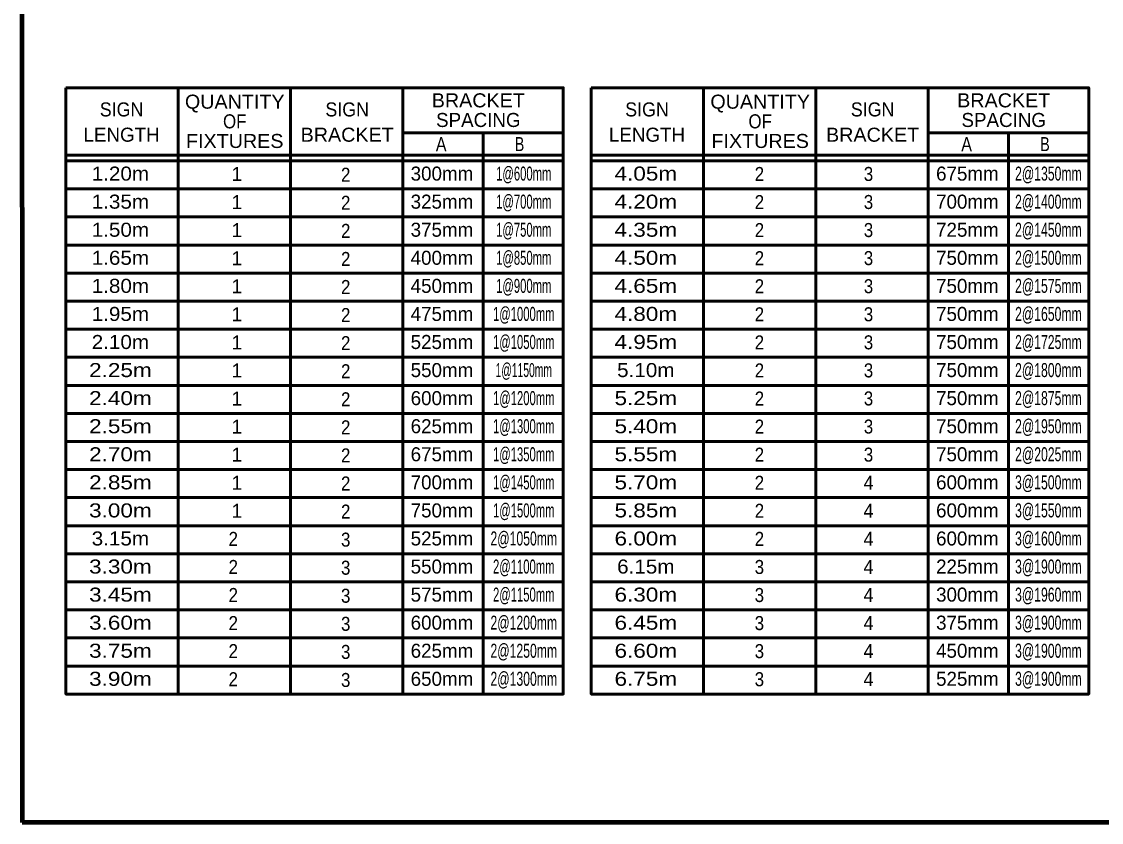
# Model space of a CAD drawing. Extents: x -94 to 762, y -50 to 494.
# Drawn here: x -36.3 to 194.5, y -38.7 to 132.5 of the extents above; entities that cross this region are included whole.
import ezdxf
from ezdxf.enums import TextEntityAlignment as Align

# ---------------------------------------------------------------- set-up
doc = ezdxf.new("R2010")
doc.units = 0
doc.header["$LTSCALE"] = 1.2
doc.layers.add('1', color=7, linetype='Continuous', lineweight=53)

msp = doc.modelspace()

# ---------------------------------------------------------------- linework, layer by layer
at = {"layer": '1'}
for p, q in [((-2.831, -11.296), (-2.831, 118.303)), ((21.169, -11.296), (21.169, 118.303)), ((45.169, -11.296), (45.169, 118.303)), ((109.451, -11.296), (109.451, 118.303)), ((133.451, -11.296), (133.451, 118.303)), ((157.451, -11.296), (157.451, 118.303)), ((45.169, 108.704), (79.451, 108.704)), ((62.31, -11.296), (62.31, 108.704)), ((157.451, 108.704), (191.733, 108.704)), ((174.592, -11.296), (174.592, 108.704)), ((-26.831, 103.904), (79.451, 103.904)), ((85.451, 103.904), (191.733, 103.904)), ((-26.831, 102.704), (79.451, 102.704)), ((85.451, 102.704), (191.733, 102.704)), ((-26.831, 96.704), (79.451, 96.704)), ((85.451, 96.704), (191.733, 96.704)), ((-26.831, 90.704), (79.451, 90.704)), ((85.451, 90.704), (191.733, 90.704)), ((-26.831, 84.704), (79.451, 84.704)), ((85.451, 84.704), (191.733, 84.704)), ((-26.831, 78.704), (79.451, 78.704)), ((85.451, 78.704), (191.733, 78.704)), ((-26.831, 72.704), (79.451, 72.704)), ((85.451, 72.704), (191.733, 72.704)), ((-26.831, 66.704), (79.451, 66.704)), ((85.451, 66.704), (191.733, 66.704)), ((-26.831, 60.704), (79.451, 60.704)), ((85.451, 60.704), (191.733, 60.704)), ((-26.831, 54.704), (79.451, 54.704)), ((85.451, 54.704), (191.733, 54.704)), ((-26.831, 48.704), (79.451, 48.704)), ((85.451, 48.704), (191.733, 48.704)), ((-26.831, 42.704), (79.451, 42.704)), ((85.451, 42.704), (191.733, 42.704)), ((-26.831, 36.703), (79.451, 36.703)), ((85.451, 36.703), (191.733, 36.703)), ((-26.831, 30.704), (79.451, 30.704)), ((85.451, 30.704), (191.733, 30.704)), ((-26.831, 24.704), (79.451, 24.704)), ((85.451, 24.704), (191.733, 24.704)), ((-26.831, 18.704), (79.451, 18.704)), ((85.451, 18.704), (191.733, 18.704)), ((-26.831, 12.704), (79.451, 12.704)), ((85.451, 12.704), (191.733, 12.704)), ((-26.831, 6.704), (79.451, 6.704)), ((85.451, 6.704), (191.733, 6.704)), ((-26.831, 0.704), (79.451, 0.704)), ((85.451, 0.704), (191.733, 0.704)), ((-26.831, -5.296), (79.451, -5.296)), ((85.451, -5.296), (191.733, -5.296))]:
    msp.add_line(p, q, dxfattribs=at)
at = {"layer": '1', "lineweight": 158}
msp.add_line((755.402, -38.728), (-36.198, -38.728), dxfattribs=at)
msp.add_lwpolyline([(755.402, 487.372), (-36.298, 487.272), (-36.198, -38.728)], dxfattribs=at)
at = {"layer": '1'}
for points in [[(-26.831, 118.303), (79.451, 118.303), (79.451, -11.296), (-26.831, -11.296)], [(85.451, 118.303), (191.733, 118.303), (191.733, -11.296), (85.451, -11.296)]]:
    msp.add_lwpolyline(points, close=True, dxfattribs=at)

# ---------------------------------------------------------------- texts
for s, width, p in [('QUANTITY', 1.05, (9.252, 113.843)), ('BRACKET', 1.05, (61.297, 114.131)), ('QUANTITY', 1.05, (121.534, 113.843)), ('BRACKET', 1.05, (173.579, 114.131)), ('SIGN', 0.95, (-14.934, 112.184)), ('SIGN', 0.95, (33.279, 112.184)), ('SIGN', 0.95, (97.348, 112.184)), ('SIGN', 0.95, (145.56, 112.184)), ('OF', 0.9, (9.252, 109.643)), ('OF', 0.9, (121.534, 109.643)), ('FIXTURES', 1.05, (9.252, 105.443)), ('BRACKET', 1.05, (33.279, 106.784)), ('FIXTURES', 1.05, (121.534, 105.443)), ('BRACKET', 1.05, (145.56, 106.784)), ('1@600mm', 0.6, (71.017, 98.47)), ('2@1350mm', 0.65, (183.121, 98.47)), ('1.20m', 1.1, (-15.186, 98.47)), ('2', 0.9, (32.961, 98.224)), ('4.05m', 1.2, (97.095, 98.47)), ('2', 0.9, (121.367, 98.384)), ('3', 0.9, (144.683, 98.402)), ('1.35m', 1.1, (-15.186, 92.47)), ('2', 0.9, (32.961, 92.224)), ('1@700mm', 0.6, (71.017, 92.47)), ('4.20m', 1.2, (97.095, 92.47)), ('2', 0.9, (121.367, 92.384)), ('3', 0.9, (144.683, 92.402)), ('2@1400mm', 0.65, (183.121, 92.47)), ('1.50m', 1.1, (-15.186, 86.47)), ('2', 0.9, (32.961, 86.224)), ('1@750mm', 0.6, (71.017, 86.47)), ('4.35m', 1.2, (97.095, 86.47)), ('2', 0.9, (121.367, 86.384)), ('3', 0.9, (144.683, 86.402)), ('2@1450mm', 0.65, (183.121, 86.47)), ('1.65m', 1.1, (-15.186, 80.47)), ('2', 0.9, (32.961, 80.224)), ('1@850mm', 0.6, (71.017, 80.47)), ('4.50m', 1.2, (97.095, 80.47)), ('2', 0.9, (121.367, 80.384)), ('3', 0.9, (144.683, 80.402)), ('2@1500mm', 0.65, (183.121, 80.47)), ('1.80m', 1.1, (-15.186, 74.47)), ('2', 0.9, (32.961, 74.224)), ('1@900mm', 0.6, (71.017, 74.47)), ('4.65m', 1.2, (97.095, 74.47)), ('2', 0.9, (121.367, 74.384)), ('3', 0.9, (144.683, 74.402)), ('2@1575mm', 0.65, (183.121, 74.47)), ('1@1000mm', 0.6, (71.017, 68.47)), ('2@1650mm', 0.65, (183.121, 68.47)), ('1.95m', 1.1, (-15.186, 68.47)), ('2', 0.9, (32.961, 68.224)), ('4.80m', 1.2, (97.095, 68.47)), ('2', 0.9, (121.367, 68.384)), ('3', 0.9, (144.683, 68.402)), ('2.10m', 1.1, (-15.186, 62.47)), ('2', 0.9, (32.961, 62.224)), ('1@1050mm', 0.6, (71.017, 62.47)), ('4.95m', 1.2, (97.095, 62.47)), ('2', 0.9, (121.367, 62.384)), ('3', 0.9, (144.683, 62.402)), ('2@1725mm', 0.65, (183.121, 62.47)), ('2.25m', 1.2, (-15.186, 56.47)), ('2', 0.9, (32.961, 56.224)), ('1@1150mm', 0.55, (71.017, 56.47)), ('5.10m', 1.1, (97.095, 56.47)), ('2', 0.9, (121.367, 56.384)), ('3', 0.9, (144.683, 56.402)), ('2@1800mm', 0.65, (183.121, 56.47)), ('2.40m', 1.2, (-15.186, 50.47)), ('2', 0.9, (32.961, 50.224)), ('1@1200mm', 0.6, (71.017, 50.47)), ('5.25m', 1.2, (97.095, 50.47)), ('2', 0.9, (121.367, 50.384)), ('3', 0.9, (144.683, 50.402)), ('2@1875mm', 0.65, (183.121, 50.47)), ('2.55m', 1.2, (-15.186, 44.47)), ('2', 0.9, (32.961, 44.224)), ('1@1300mm', 0.6, (71.017, 44.47)), ('5.40m', 1.2, (97.095, 44.47)), ('2', 0.9, (121.367, 44.384)), ('3', 0.9, (144.683, 44.402)), ('2@1950mm', 0.65, (183.121, 44.47)), ('1@1350mm', 0.6, (71.017, 38.47)), ('2@2025mm', 0.65, (183.121, 38.47)), ('2.70m', 1.2, (-15.186, 38.47)), ('2', 0.9, (32.961, 38.224)), ('5.55m', 1.2, (97.095, 38.47)), ('2', 0.9, (121.367, 38.384)), ('3', 0.9, (144.683, 38.402)), ('2.85m', 1.2, (-15.186, 32.47)), ('2', 0.9, (32.961, 32.224)), ('1@1450mm', 0.6, (71.017, 32.47)), ('5.70m', 1.2, (97.095, 32.47)), ('2', 0.9, (121.367, 32.384)), ('4', 0.95, (144.683, 32.402)), ('3@1500mm', 0.65, (183.121, 32.47)), ('3.00m', 1.2, (-15.186, 26.47)), ('2', 0.9, (32.961, 26.224)), ('1@1500mm', 0.6, (71.017, 26.47)), ('5.85m', 1.2, (97.095, 26.47)), ('2', 0.9, (121.367, 26.384)), ('4', 0.95, (144.683, 26.402)), ('3@1550mm', 0.65, (183.121, 26.47)), ('3.15m', 1.1, (-15.186, 20.47)), ('2', 0.9, (8.934, 20.384)), ('3', 0.9, (32.961, 20.224)), ('2@1050mm', 0.65, (71.017, 20.47)), ('6.00m', 1.2, (97.095, 20.47)), ('2', 0.9, (121.367, 20.384)), ('4', 0.95, (144.683, 20.402)), ('3@1600mm', 0.65, (183.121, 20.47)), ('3.30m', 1.2, (-15.186, 14.47)), ('2', 0.9, (8.934, 14.384)), ('3', 0.9, (32.961, 14.224)), ('2@1100mm', 0.6, (71.017, 14.47)), ('6.15m', 1.1, (97.095, 14.47)), ('3', 0.9, (121.367, 14.384)), ('4', 0.95, (144.683, 14.402)), ('3@1900mm', 0.65, (183.121, 14.47)), ('2@1150mm', 0.6, (71.017, 8.47)), ('3@1960mm', 0.65, (183.121, 8.47)), ('3.45m', 1.2, (-15.186, 8.47)), ('2', 0.9, (8.934, 8.384)), ('3', 0.9, (32.961, 8.224)), ('6.30m', 1.2, (97.095, 8.47)), ('3', 0.9, (121.367, 8.384)), ('4', 0.95, (144.683, 8.402)), ('3.60m', 1.2, (-15.186, 2.47)), ('2', 0.9, (8.934, 2.384)), ('3', 0.9, (32.961, 2.224)), ('2@1200mm', 0.65, (71.017, 2.47)), ('6.45m', 1.2, (97.095, 2.47)), ('3', 0.9, (121.367, 2.384)), ('4', 0.95, (144.683, 2.402)), ('3@1900mm', 0.65, (183.121, 2.47)), ('3.75m', 1.2, (-15.186, -3.53)), ('2', 0.9, (8.934, -3.616)), ('3', 0.9, (32.961, -3.776)), ('2@1250mm', 0.65, (71.017, -3.53)), ('6.60m', 1.2, (97.095, -3.53)), ('3', 0.9, (121.367, -3.616)), ('4', 0.95, (144.683, -3.598)), ('3@1900mm', 0.65, (183.121, -3.53)), ('3.90m', 1.2, (-15.186, -9.53)), ('2', 0.9, (8.934, -9.616)), ('3', 0.9, (32.961, -9.776)), ('2@1300mm', 0.65, (71.017, -9.53)), ('6.75m', 1.2, (97.095, -9.53)), ('3', 0.9, (121.367, -9.616)), ('4', 0.95, (144.683, -9.598)), ('3@1900mm', 0.65, (183.121, -9.53))]:
    msp.add_text(s, height=3, dxfattribs=dict(at, width=width)).set_placement(p, align=Align.CENTER)
for s, p in [('SPACING', (61.297, 109.931)), ('SPACING', (173.579, 109.931)), ('LENGTH', (-14.934, 106.784)), ('LENGTH', (97.348, 106.784)), ('1', (9.705, 98.384)), ('300mm', (53.528, 98.47)), ('675mm', (165.809, 98.47)), ('1', (9.705, 92.384)), ('325mm', (53.528, 92.47)), ('700mm', (165.809, 92.47)), ('1', (9.705, 86.384)), ('375mm', (53.528, 86.47)), ('725mm', (165.809, 86.47)), ('1', (9.705, 80.384)), ('400mm', (53.528, 80.47)), ('750mm', (165.809, 80.47)), ('1', (9.705, 74.384)), ('450mm', (53.528, 74.47)), ('750mm', (165.809, 74.47)), ('1', (9.705, 68.384)), ('475mm', (53.528, 68.47)), ('750mm', (165.809, 68.47)), ('1', (9.705, 62.384)), ('525mm', (53.528, 62.47)), ('750mm', (165.809, 62.47)), ('1', (9.705, 56.384)), ('550mm', (53.528, 56.47)), ('750mm', (165.809, 56.47)), ('1', (9.705, 50.384)), ('600mm', (53.528, 50.47)), ('750mm', (165.809, 50.47)), ('1', (9.705, 44.384)), ('625mm', (53.528, 44.47)), ('750mm', (165.809, 44.47)), ('1', (9.705, 38.384)), ('675mm', (53.528, 38.47)), ('750mm', (165.809, 38.47)), ('1', (9.705, 32.384)), ('700mm', (53.528, 32.47)), ('600mm', (165.809, 32.47)), ('1', (9.705, 26.384)), ('750mm', (53.528, 26.47)), ('600mm', (165.809, 26.47)), ('525mm', (53.528, 20.47)), ('600mm', (165.809, 20.47)), ('550mm', (53.528, 14.47)), ('225mm', (165.809, 14.47)), ('575mm', (53.528, 8.47)), ('300mm', (165.809, 8.47)), ('600mm', (53.528, 2.47)), ('375mm', (165.809, 2.47)), ('625mm', (53.528, -3.53)), ('450mm', (165.809, -3.53)), ('650mm', (53.528, -9.53)), ('525mm', (165.809, -9.53))]:
    msp.add_text(s, height=3, dxfattribs=at).set_placement(p, align=Align.CENTER)
for s, width, p in [('A', 0.85, (52.227, 104.758)), ('B', 0.75, (69.114, 104.776)), ('A', 0.85, (164.509, 104.758)), ('B', 0.75, (181.396, 104.776))]:
    msp.add_text(s, height=3, dxfattribs=dict(at, width=width)).set_placement(p)

doc.saveas('drawing.dxf')
